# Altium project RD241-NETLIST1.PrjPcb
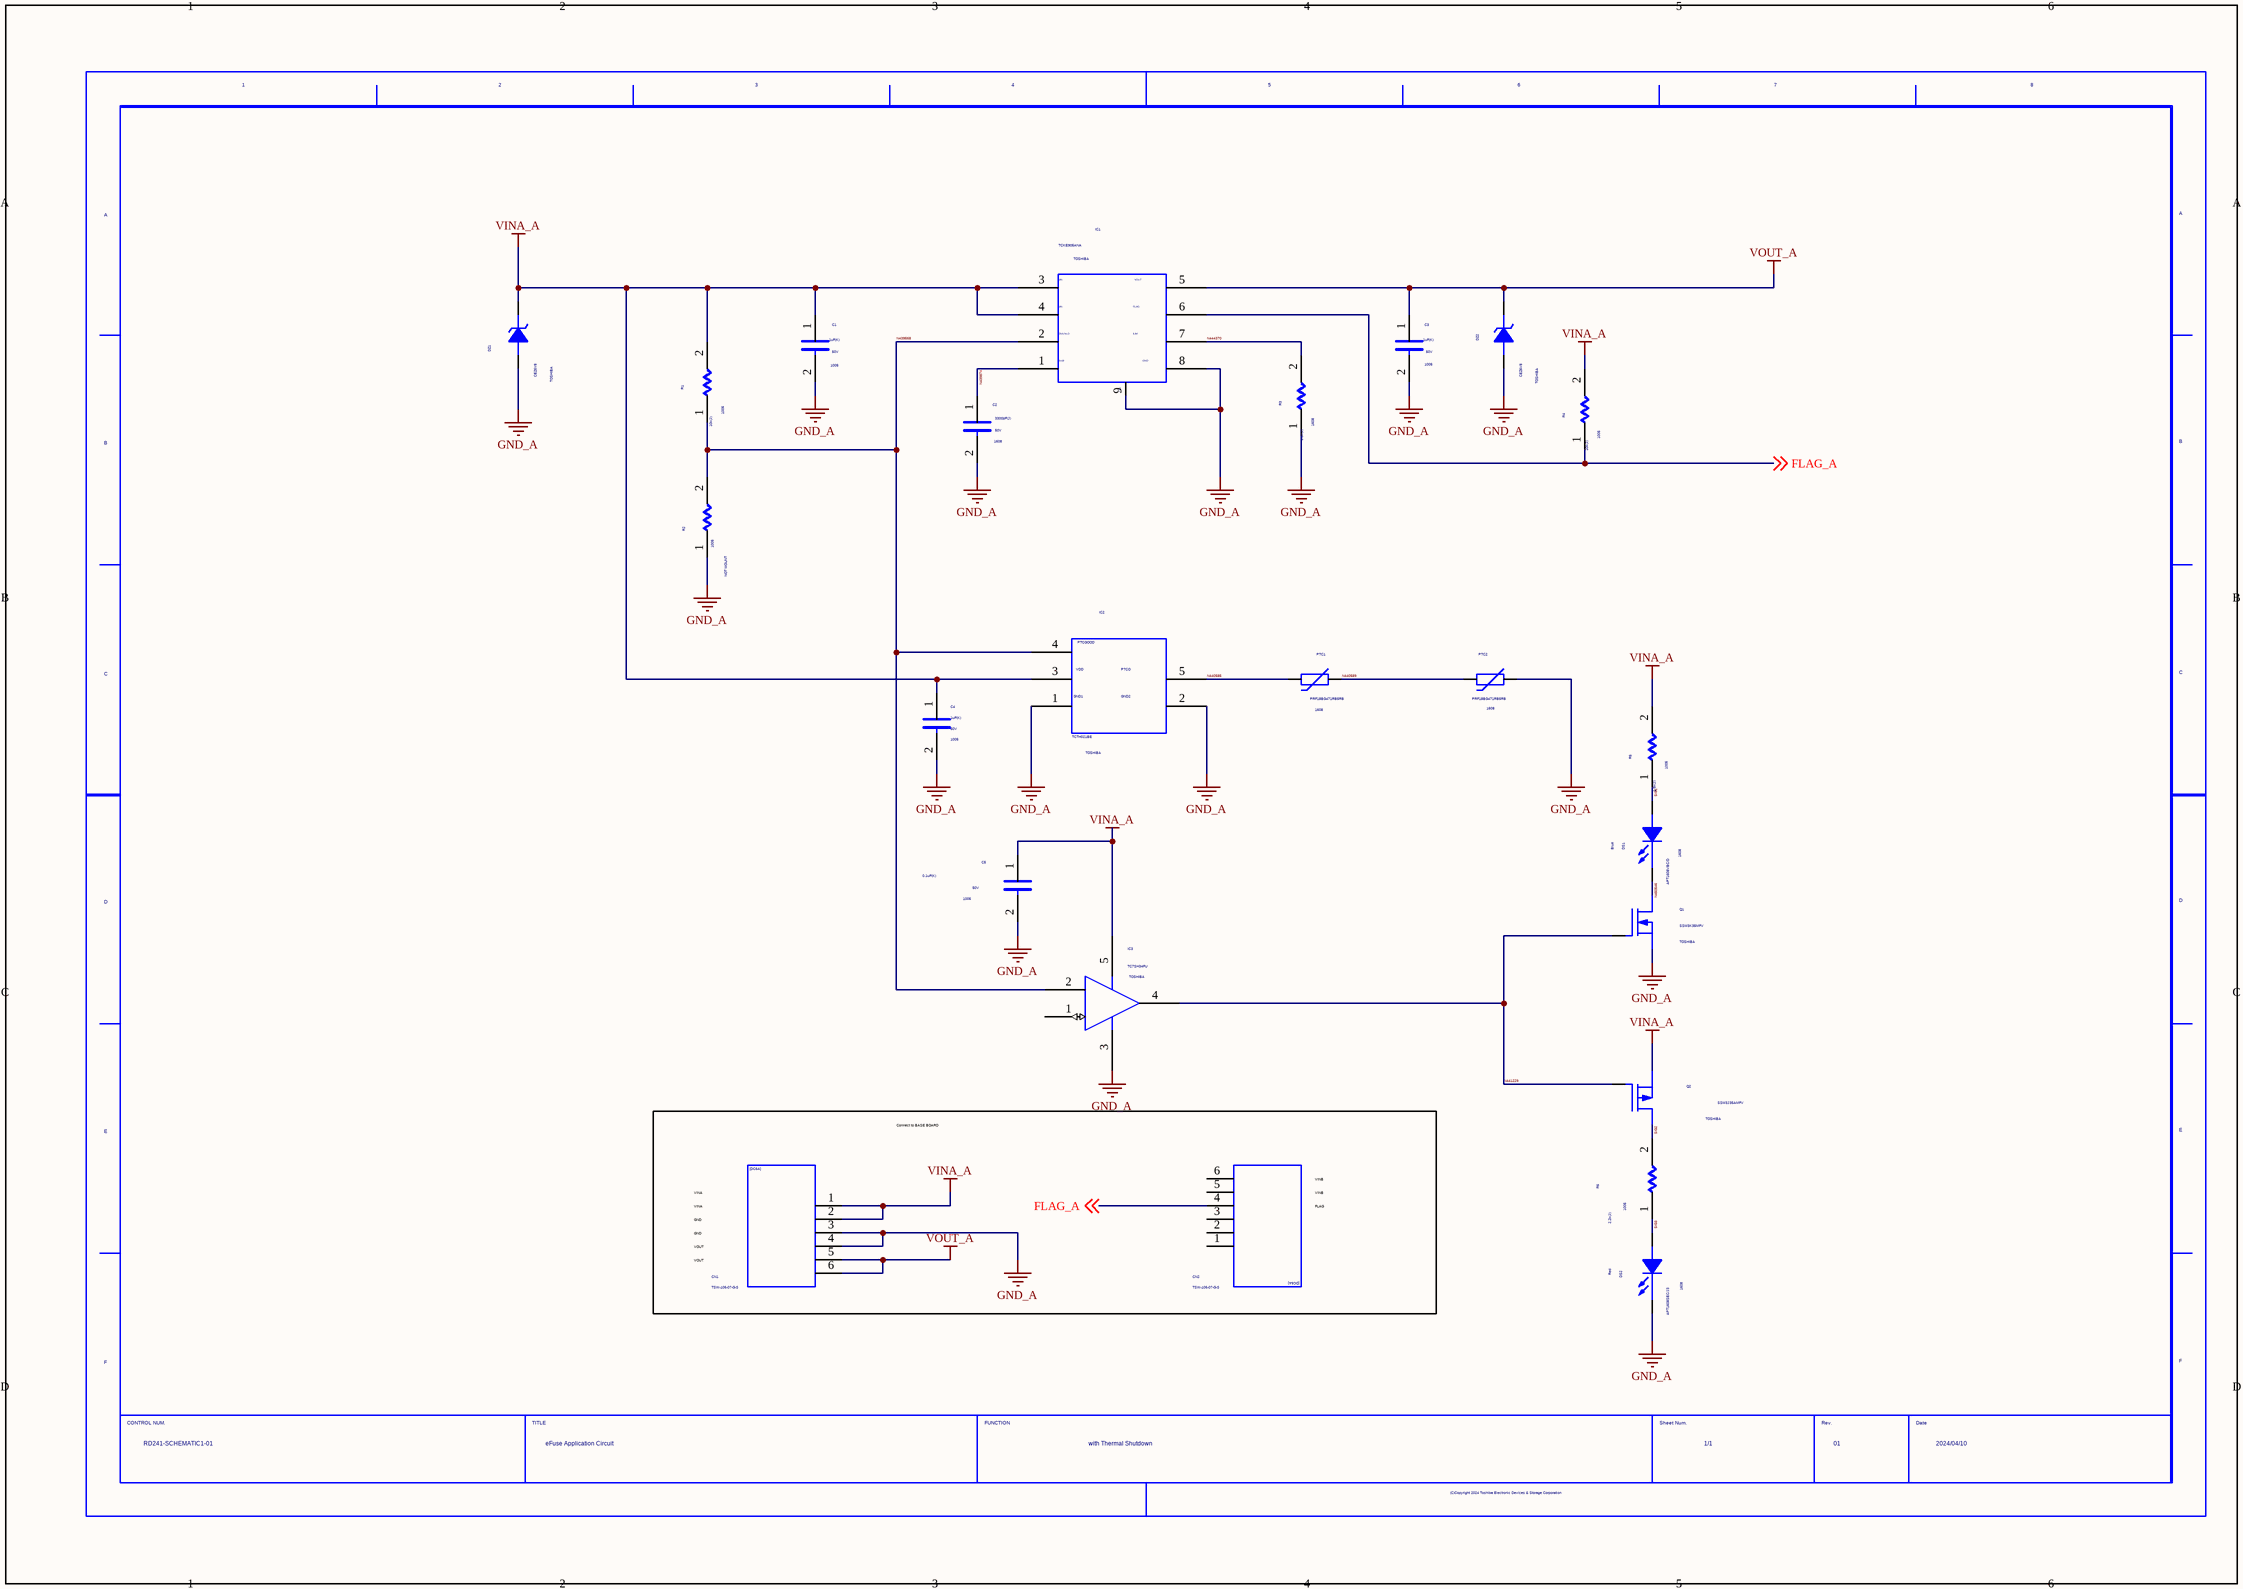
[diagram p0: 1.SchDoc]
1 sheet, 25 parts. Net scope: global (net labels, ports and power ports of the same name join across sheets).

## Sheet 1.SchDoc
size 420 x 297 mm

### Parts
C1  SIZECODESMD: 1005  VAL2: 50V  VAL1: 1uF(K)  (hidden comment: C)
C2  SIZECODESMD: 1608  VAL2: 50V  VAL1: 3300pF(J)  (hidden comment: C)
C3  SIZECODESMD: 1005  VAL2: 50V  VAL1: 1uF(K)  (hidden comment: C)
C4  SIZECODESMD: 1005  VAL2: 50V  VAL1: 1uF(K)  (hidden comment: C)
C5  SIZECODESMD: 1005  VAL2: 50V  VAL1: 0.1uF(K)  (hidden comment: C)
CN1  VAL3: TSW-106-07-G-S  (hidden comment: DC6A)
CN2  VAL3: TSW-106-07-G-S  (hidden comment: DC6A)
DS1  SIZECODESMD: 1608  VAL3: APT1608VBC/D  VAL1: Blue  (hidden comment: CQX14_TO)
DS2  SIZECODESMD: 1608  VAL3: APT1608SEC/J3  VAL1: Red  (hidden comment: CQX14_TO)
DZ1  USERCOMPTEXT3: TOSHIBA  VAL3: CEZ6V8  (hidden comment: BZX84C10_SOT)
DZ2  USERCOMPTEXT3: TOSHIBA  VAL3: CEZ6V8  (hidden comment: BZX84C10_SOT)
IC1  USERCOMPTEXT3: TOSHIBA  VAL3: TCKE905ANA  (hidden comment: EL2140_0)
IC2  USERCOMPTEXT3: TOSHIBA  VAL3: TCTH021BE  (hidden comment: EL2140_1)
IC3  USERCOMPTEXT3: TOSHIBA  VAL3: TC7SH34FU  (hidden comment: TC4S584F_SSOP_1)
PTC1  SIZECODESMD: 1608  VAL3: PRF18BG471RB5RB  (hidden comment: VARISTOR_SYM)
PTC2  SIZECODESMD: 1608  VAL3: PRF18BG471RB5RB  (hidden comment: VARISTOR_SYM)
Q1  USERCOMPTEXT3: TOSHIBA  VAL3: SSM3K35MFV  (hidden comment: ZVN3306A_TO)
Q2  USERCOMPTEXT3: TOSHIBA  VAL3: SSM3J35AMFV  (hidden comment: ZVP0545_TO)
R1  SIZECODESMD: 1005  VAL1: 10k(J)  (hidden comment: R)
R2  NOTMOUNT: NOT MOUNT  SIZECODESMD: 1005  (hidden comment: R)
R3  SIZECODESMD: 1608  VAL1: 1.8k(J)  (hidden comment: R)
R4  SIZECODESMD: 1005  VAL1: 10k(J)  (hidden comment: R)
R5  SIZECODESMD: 1005  VAL1: 1.5k(J)  (hidden comment: R)
R6  SIZECODESMD: 1005  VAL1: 2.2k(J)  (hidden comment: R)
U?  DATE: 2024/04/10  REVISION: 01  SHEETNUMBER: 1/1  TITLE: eFuse Application Circuit  FUNCTION: with Thermal Shutdown  DRAWINGNUMBER: RD241-SCHEMATIC1-01  (hidden comment: WAKU_DEF100)

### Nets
GND_A: C1.2 C2.2 C3.2 C4.2 C5.2 CN1.3 CN1.4 DS2.1(CATHODE) DZ1.1(ANODE) DZ2.1(ANODE) IC1.8 IC1.9 IC2.1 IC2.2 IC3.3 PTC2.1 Q1.3(S) R2.1 R3.1
VINA_A: C1.1 C4.1 C5.1 CN1.1 CN1.2 DZ1.3(CATHODE) IC1.3 IC1.4 IC2.3 IC3.5 Q2.3(S) R1.2 R4.2 R5.2
VOUT_A: C3.1 CN1.5 CN1.6 DZ2.3(CATHODE) IC1.5
FLAG_A: CN2.4 IC1.6 R4.1 ; off-sheet FLAG_A
N439568: IC1.2 IC2.4 IC3.2 R1.1 R2.2
N439874: C2.1 IC1.1
N440585: IC2.5 PTC1.2
N440589: PTC1.1 PTC2.2
N441229: IC3.4 Q1.2(G) Q2.2(G)
N444370: IC1.7 R3.2
N450546: DS1.1(CATHODE) Q1.1(D)
SIG1: DS1.3(ANODE) R5.1
SIG2: Q2.1(D) R6.2
SIG3: DS2.3(ANODE) R6.1

Not connected (* = marked no-connect by the designer): CN2 1 2 3 5 6; IC3 1

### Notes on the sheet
- Connect to BASE BOARD
- VINA
- VINB
- FLAG
- VOUT
- GND

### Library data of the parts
C1 = C: TIME: 12:45:10; UPDATEUSER: t5459927; SAVECOUNT: 2; ORIGINALSYMBOLORIGIN: (0,0); __TIME_0__: 1711511110; __FILE_0__: C:/Users/t5459927/Desktop/RD228/RD241_242/SMB006/C.smb; __HOST_0__: t5459927-02; __$Database_ID__: Z-2ed5c0e2-f3bf-4eaa-903b-98ed9c52cb7a; LAYOUTNAME: Z-4ffcc391-4683-4a73-b3b5-9ac0d6e3701d.cmp24; COMPONENTNAME: C_C; VAL3: GRT188R61H105KE13D
C2 = C: TIME: 12:45:10; UPDATEUSER: t5459927; SAVECOUNT: 2; ORIGINALSYMBOLORIGIN: (0,0); __TIME_0__: 1711511110; __FILE_0__: C:/Users/t5459927/Desktop/RD228/RD241_242/SMB006/C.smb; __HOST_0__: t5459927-02; __$Database_ID__: Z-2ed5c0e2-f3bf-4eaa-903b-98ed9c52cb7a; LAYOUTNAME: Z-4ffcc391-4683-4a73-b3b5-9ac0d6e3701d.cmp7; COMPONENTNAME: C_C; VAL3: GCM188R71H332KA37D
C3 = C: TIME: 12:45:10; UPDATEUSER: t5459927; SAVECOUNT: 2; ORIGINALSYMBOLORIGIN: (0,0); __TIME_0__: 1711511110; __FILE_0__: C:/Users/t5459927/Desktop/RD228/RD241_242/SMB006/C.smb; __HOST_0__: t5459927-02; __$Database_ID__: Z-2ed5c0e2-f3bf-4eaa-903b-98ed9c52cb7a; LAYOUTNAME: Z-4ffcc391-4683-4a73-b3b5-9ac0d6e3701d.cmp5; COMPONENTNAME: C_C; VAL3: GRT188R61H105KE13D
C4 = C: TIME: 12:45:10; UPDATEUSER: t5459927; SAVECOUNT: 2; ORIGINALSYMBOLORIGIN: (0,0); __TIME_0__: 1711511110; __FILE_0__: C:/Users/t5459927/Desktop/RD228/RD241_242/SMB006/C.smb; __HOST_0__: t5459927-02; __$Database_ID__: Z-2ed5c0e2-f3bf-4eaa-903b-98ed9c52cb7a; LAYOUTNAME: Z-4ffcc391-4683-4a73-b3b5-9ac0d6e3701d.cmp15; COMPONENTNAME: C_C; VAL3: GRT188R61H105KE13D
C5 = C: TIME: 12:45:10; UPDATEUSER: t5459927; SAVECOUNT: 2; ORIGINALSYMBOLORIGIN: (0,0); __TIME_0__: 1711511110; __FILE_0__: C:/Users/t5459927/Desktop/RD228/RD241_242/SMB006/C.smb; __HOST_0__: t5459927-02; __$Database_ID__: Z-2ed5c0e2-f3bf-4eaa-903b-98ed9c52cb7a; LAYOUTNAME: Z-4ffcc391-4683-4a73-b3b5-9ac0d6e3701d.cmp18; COMPONENTNAME: C_C; VAL3: GRM155R71H104KE14D
CN1 = DC6A: TIME: 13:28:28; UPDATEUSER: e1023210; UPDATETIME: 18:37:18; SAVECOUNT: 24; SAVEAREA0: -19103,0,39483,27940; ORIGINALSYMBOLORIGIN: (0,0); LAYOUTNAME: Z-4ffcc391-4683-4a73-b3b5-9ac0d6e3701d.cmp2; COMPONENTNAME: DC6A_DC6A; VAL2: 2.54mm
CN2 = DC6A: TIME: 13:28:28; UPDATEUSER: e1023210; UPDATETIME: 18:37:18; SAVECOUNT: 24; SAVEAREA0: -19103,0,39483,27940; ORIGINALSYMBOLORIGIN: (0,0); LAYOUTNAME: Z-4ffcc391-4683-4a73-b3b5-9ac0d6e3701d.cmp19; COMPONENTNAME: DC6A_DC6A; VAL2: 2.54mm
DS1 = CQX14_TO: TIME: 12:45:09; UPDATEUSER: t5459927; SAVECOUNT: 2; __TIME_0__: 1711511109; __FILE_0__: C:/Users/t5459927/Desktop/RD228/RD241_242/DISCRETE/CQX14_TO.smb; __HOST_0__: t5459927-02; __$Database_ID__: Z-1cb6e29b-ad43-4461-94ab-d8e4d2707aaf; OriginalSymbolOrigin: (0,0); LAYOUTNAME: Z-4ffcc391-4683-4a73-b3b5-9ac0d6e3701d.cmp1; COMPONENTNAME: CQX14_TO_CQX14_TO; VAL2: 3.3V/20mA
DS2 = CQX14_TO: TIME: 12:45:09; UPDATEUSER: t5459927; SAVECOUNT: 2; __TIME_0__: 1711511109; __FILE_0__: C:/Users/t5459927/Desktop/RD228/RD241_242/DISCRETE/CQX14_TO.smb; __HOST_0__: t5459927-02; __$Database_ID__: Z-1cb6e29b-ad43-4461-94ab-d8e4d2707aaf; OriginalSymbolOrigin: (0,0); LAYOUTNAME: Z-4ffcc391-4683-4a73-b3b5-9ac0d6e3701d.cmp21; COMPONENTNAME: CQX14_TO_CQX14_TO; VAL2: 2.2V/20mA
DZ1 = BZX84C10_SOT: TIME: 12:45:09; UPDATEUSER: t5459927; SAVECOUNT: 2; __TIME_0__: 1711511109; __FILE_0__: C:/Users/t5459927/Desktop/RD228/RD241_242/DISCRETE/BZX84C10_SOT.smb; __HOST_0__: t5459927-02; __$Database_ID__: Z-4d996314-a8f2-4553-8b05-67113f3b3349; OriginalSymbolOrigin: (0,0); LAYOUTNAME: Z-4ffcc391-4683-4a73-b3b5-9ac0d6e3701d.cmp4; COMPONENTNAME: BZX84C10_SOT_BZX84C10_SOT; VAL2: 6.4V-7.2V
DZ2 = BZX84C10_SOT: TIME: 12:45:09; UPDATEUSER: t5459927; SAVECOUNT: 2; __TIME_0__: 1711511109; __FILE_0__: C:/Users/t5459927/Desktop/RD228/RD241_242/DISCRETE/BZX84C10_SOT.smb; __HOST_0__: t5459927-02; __$Database_ID__: Z-4d996314-a8f2-4553-8b05-67113f3b3349; OriginalSymbolOrigin: (0,0); LAYOUTNAME: Z-4ffcc391-4683-4a73-b3b5-9ac0d6e3701d.cmp14; COMPONENTNAME: BZX84C10_SOT_BZX84C10_SOT; VAL2: 6.4V-7.2V
IC1 = EL2140_0: TIME: 12:45:12; UPDATEUSER: t5459927; UPDATETIME: 14:48:14; SAVECOUNT: 4; OriginalSymbolOrigin: (7620,0); LAYOUTNAME: Z-4ffcc391-4683-4a73-b3b5-9ac0d6e3701d.cmp59
IC2 = EL2140_1: TIME: 12:45:11; UPDATEUSER: t5459927; UPDATETIME: 14:01:54; SAVECOUNT: 3; OriginalSymbolOrigin: (0,0); LAYOUTNAME: Z-4ffcc391-4683-4a73-b3b5-9ac0d6e3701d.cmp55
IC3 = TC4S584F_SSOP_1: TIME: 12:45:11; UPDATEUSER: t5459927; UPDATETIME: 14:51:38; SAVECOUNT: 3; OriginalSymbolOrigin: (0,0); LAYOUTNAME: Z-4ffcc391-4683-4a73-b3b5-9ac0d6e3701d.cmp60
PTC1 = VARISTOR_SYM: TIME: 12:45:09; UPDATEUSER: t5459927; SAVECOUNT: 2; __TIME_0__: 1711511109; __FILE_0__: C:/Users/t5459927/Desktop/RD228/RD241_242/DISCRETE/VARISTOR_SYM.smb; __HOST_0__: t5459927-02; __$Database_ID__: Z-408d415e-1fb1-46aa-bdfc-9f261eeb8e75; OriginalSymbolOrigin: (0,0); LAYOUTNAME: Z-4ffcc391-4683-4a73-b3b5-9ac0d6e3701d.cmp20; COMPONENTNAME: VARISTOR_SYM_VARISTOR_SYM
PTC2 = VARISTOR_SYM: TIME: 12:45:09; UPDATEUSER: t5459927; SAVECOUNT: 2; __TIME_0__: 1711511109; __FILE_0__: C:/Users/t5459927/Desktop/RD228/RD241_242/DISCRETE/VARISTOR_SYM.smb; __HOST_0__: t5459927-02; __$Database_ID__: Z-408d415e-1fb1-46aa-bdfc-9f261eeb8e75; OriginalSymbolOrigin: (0,0); LAYOUTNAME: Z-4ffcc391-4683-4a73-b3b5-9ac0d6e3701d.cmp3; COMPONENTNAME: VARISTOR_SYM_VARISTOR_SYM
Q1 = ZVN3306A_TO: TIME: 12:45:10; UPDATEUSER: t5459927; SAVECOUNT: 2; __TIME_0__: 1711511110; __FILE_0__: C:/Users/t5459927/Desktop/RD228/RD241_242/TRANSISTOR/ZVN3306A_TO.smb; __HOST_0__: t5459927-02; __$Database_ID__: Z-67d2e6f0-db45-4aeb-8b2f-a8031d5274fb; OriginalSymbolOrigin: (0,5080); LAYOUTNAME: Z-4ffcc391-4683-4a73-b3b5-9ac0d6e3701d.cmp6; COMPONENTNAME: ZVN3306A_TO_ZVN3306A_TO
Q2 = ZVP0545_TO: TIME: 12:45:10; UPDATEUSER: t5459927; SAVECOUNT: 2; __TIME_0__: 1711511110; __FILE_0__: C:/Users/t5459927/Desktop/RD228/RD241_242/TRANSISTOR/ZVP0545_TO.smb; __HOST_0__: t5459927-02; __$Database_ID__: Z-0ccab0bb-bbd5-4164-9450-f350f899c1c7; OriginalSymbolOrigin: (0,5080); LAYOUTNAME: Z-4ffcc391-4683-4a73-b3b5-9ac0d6e3701d.cmp13; COMPONENTNAME: ZVP0545_TO_ZVP0545_TO
R1 = R: TIME: 12:45:10; UPDATEUSER: t5459927; SAVECOUNT: 2; ORIGINALSYMBOLORIGIN: (0,0); __TIME_0__: 1711511110; __FILE_0__: C:/Users/t5459927/Desktop/RD228/RD241_242/WORK_EDIF_SERVER1_6KW_SD_SMB007/R.smb; __HOST_0__: t5459927-02; __$Database_ID__: Z-26c83a47-3c15-4f79-b1a7-540f9e8407cf; LAYOUTNAME: Z-4ffcc391-4683-4a73-b3b5-9ac0d6e3701d.cmp23; COMPONENTNAME: R_R; VAL3: RK73H1ETTP1002F; VAL2: 100mW
R2 = R: TIME: 12:45:10; UPDATEUSER: t5459927; SAVECOUNT: 2; ORIGINALSYMBOLORIGIN: (0,0); __TIME_0__: 1711511110; __FILE_0__: C:/Users/t5459927/Desktop/RD228/RD241_242/WORK_EDIF_SERVER1_6KW_SD_SMB007/R.smb; __HOST_0__: t5459927-02; __$Database_ID__: Z-26c83a47-3c15-4f79-b1a7-540f9e8407cf; LAYOUTNAME: Z-4ffcc391-4683-4a73-b3b5-9ac0d6e3701d.cmp9; COMPONENTNAME: R_R; VAL3: RK73H1ETTP3901F; VAL2: 100mW; VAL1: 3.9k(J)
R3 = R: TIME: 12:45:10; UPDATEUSER: t5459927; SAVECOUNT: 2; ORIGINALSYMBOLORIGIN: (0,0); __TIME_0__: 1711511110; __FILE_0__: C:/Users/t5459927/Desktop/RD228/RD241_242/WORK_EDIF_SERVER1_6KW_SD_SMB007/R.smb; __HOST_0__: t5459927-02; __$Database_ID__: Z-26c83a47-3c15-4f79-b1a7-540f9e8407cf; LAYOUTNAME: Z-4ffcc391-4683-4a73-b3b5-9ac0d6e3701d.cmp8; COMPONENTNAME: R_R; VAL3: RK73B1JTTD182J; VAL2: 100mW
R4 = R: TIME: 12:45:10; UPDATEUSER: t5459927; SAVECOUNT: 2; ORIGINALSYMBOLORIGIN: (0,0); __TIME_0__: 1711511110; __FILE_0__: C:/Users/t5459927/Desktop/RD228/RD241_242/WORK_EDIF_SERVER1_6KW_SD_SMB007/R.smb; __HOST_0__: t5459927-02; __$Database_ID__: Z-26c83a47-3c15-4f79-b1a7-540f9e8407cf; LAYOUTNAME: Z-4ffcc391-4683-4a73-b3b5-9ac0d6e3701d.cmp10; COMPONENTNAME: R_R; VAL3: RK73B1ETTP103J; VAL2: 100mW
R5 = R: TIME: 12:45:10; UPDATEUSER: t5459927; SAVECOUNT: 2; ORIGINALSYMBOLORIGIN: (0,0); __TIME_0__: 1711511110; __FILE_0__: C:/Users/t5459927/Desktop/RD228/RD241_242/WORK_EDIF_SERVER1_6KW_SD_SMB007/R.smb; __HOST_0__: t5459927-02; __$Database_ID__: Z-26c83a47-3c15-4f79-b1a7-540f9e8407cf; LAYOUTNAME: Z-4ffcc391-4683-4a73-b3b5-9ac0d6e3701d.cmp25; COMPONENTNAME: R_R; VAL3: RK73B1ETTP152J; VAL2: 100mW
R6 = R: TIME: 12:45:10; UPDATEUSER: t5459927; SAVECOUNT: 2; ORIGINALSYMBOLORIGIN: (0,0); __TIME_0__: 1711511110; __FILE_0__: C:/Users/t5459927/Desktop/RD228/RD241_242/WORK_EDIF_SERVER1_6KW_SD_SMB007/R.smb; __HOST_0__: t5459927-02; __$Database_ID__: Z-26c83a47-3c15-4f79-b1a7-540f9e8407cf; LAYOUTNAME: Z-4ffcc391-4683-4a73-b3b5-9ac0d6e3701d.cmp11; COMPONENTNAME: R_R; VAL3: RK73B1ETTP222J; VAL2: 100mW
U? = WAKU_DEF100A: TIME: 14:30:25; UPDATEUSER: cae; UPDATETIME: 18:29:18; SAVECOUNT: 3; PLOTTIME: HH:MM; SAVEAREA0: -97960,-271444,497068,-316; ORIGINALSYMBOLORIGIN: (0,0); __TIME_0__: 1711511106; __USER_0__: t5459927; __FILE_0__: C:/Users/t5459927/Desktop/RD228/RD241_242/SMB008/WAKU_DEF100.smb; __HOST_0__: t5459927-02; __$Database_ID__: Z-c202f42d-4400-46ba-87ce-01e3b7045849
